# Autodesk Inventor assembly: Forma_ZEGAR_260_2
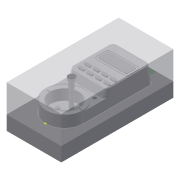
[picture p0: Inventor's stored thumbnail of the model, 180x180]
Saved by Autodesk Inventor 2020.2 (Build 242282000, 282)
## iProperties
Created: 2015-01
Part Number: Forma_ZEGAR_260_2
Document SubType Name: Assembly
Designer: F.Stasiak
Catalog Web Link: www.expertbooks.pl
Manager: www.cadconsulting.pl
Company: Fabian Stasiak CAD Consulting
Author: F.Stasiak
Subject: Zbiór ćwiczeń. Autodesk Inventor 2020. Kurs Professional
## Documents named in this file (3)
- C:\2020_Kurs_Professional\R6 Formy\Forma_ZEGAR_260_2.iam
- C:\2020_Kurs_Professional\R6 Formy\Komponenty\Forma_ZEGAR_260_ZEGAR_260_LY.iam
- C:\2020_Kurs_Professional\R6 Formy\Komponenty\Forma_ZEGAR_260_RG.ipt
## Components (2 placed, 2 different names)
1. Forma_ZEGAR_260_ZEGAR_260_LY:1 [sub-assembly] — Równoległy:1, Równoległy:2, Równoległy:3
2. Forma_ZEGAR_260_RG:1
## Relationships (3: Flush 3)
- Równoległy:1 [Flush]: Forma_ZEGAR_260_ZEGAR_260_LY:1
- Równoległy:2 [Flush]: Forma_ZEGAR_260_ZEGAR_260_LY:1
- Równoległy:3 [Flush]: Forma_ZEGAR_260_ZEGAR_260_LY:1
